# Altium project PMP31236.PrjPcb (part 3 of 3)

## Sheet PMP31236RevA_Supply_U.SchDoc: PMP30750_RevB
size 431 x 279 mm; Date: Not shown in title block; ApprovedBy: Not shown in title block; CheckedBy: Not shown in title block; Author: Not shown in title block; CompanyName: Not shown in title block; Engineer: Not shown in title block; Organization: Not shown in title block; Address1: Not shown in title block; Address2: Not shown in title block; Address3: Not shown in title block; Address4: Not shown in title block; DocumentNumber: 8; Revision: Use project parameter SCH_Rev; SheetNumber: 8; SheetTotal: 11; PageSetup: Record=PageOptions¦CenterHorizontal=True¦CenterVertical=True¦PrintScale=0.70¦XCorrection=1.00¦YCorrection=1.00¦PrintKind=0¦BorderSize=5000000¦LeftOffset=0¦BottomOffset=0¦Orientation=2¦PaperLength=1000¦PaperWidth=1000¦Scale=100¦PaperSource=15¦PrintQuality=600¦MediaType=1¦DitherType=10¦PaperKind=A4¦PrintScaleMode=1
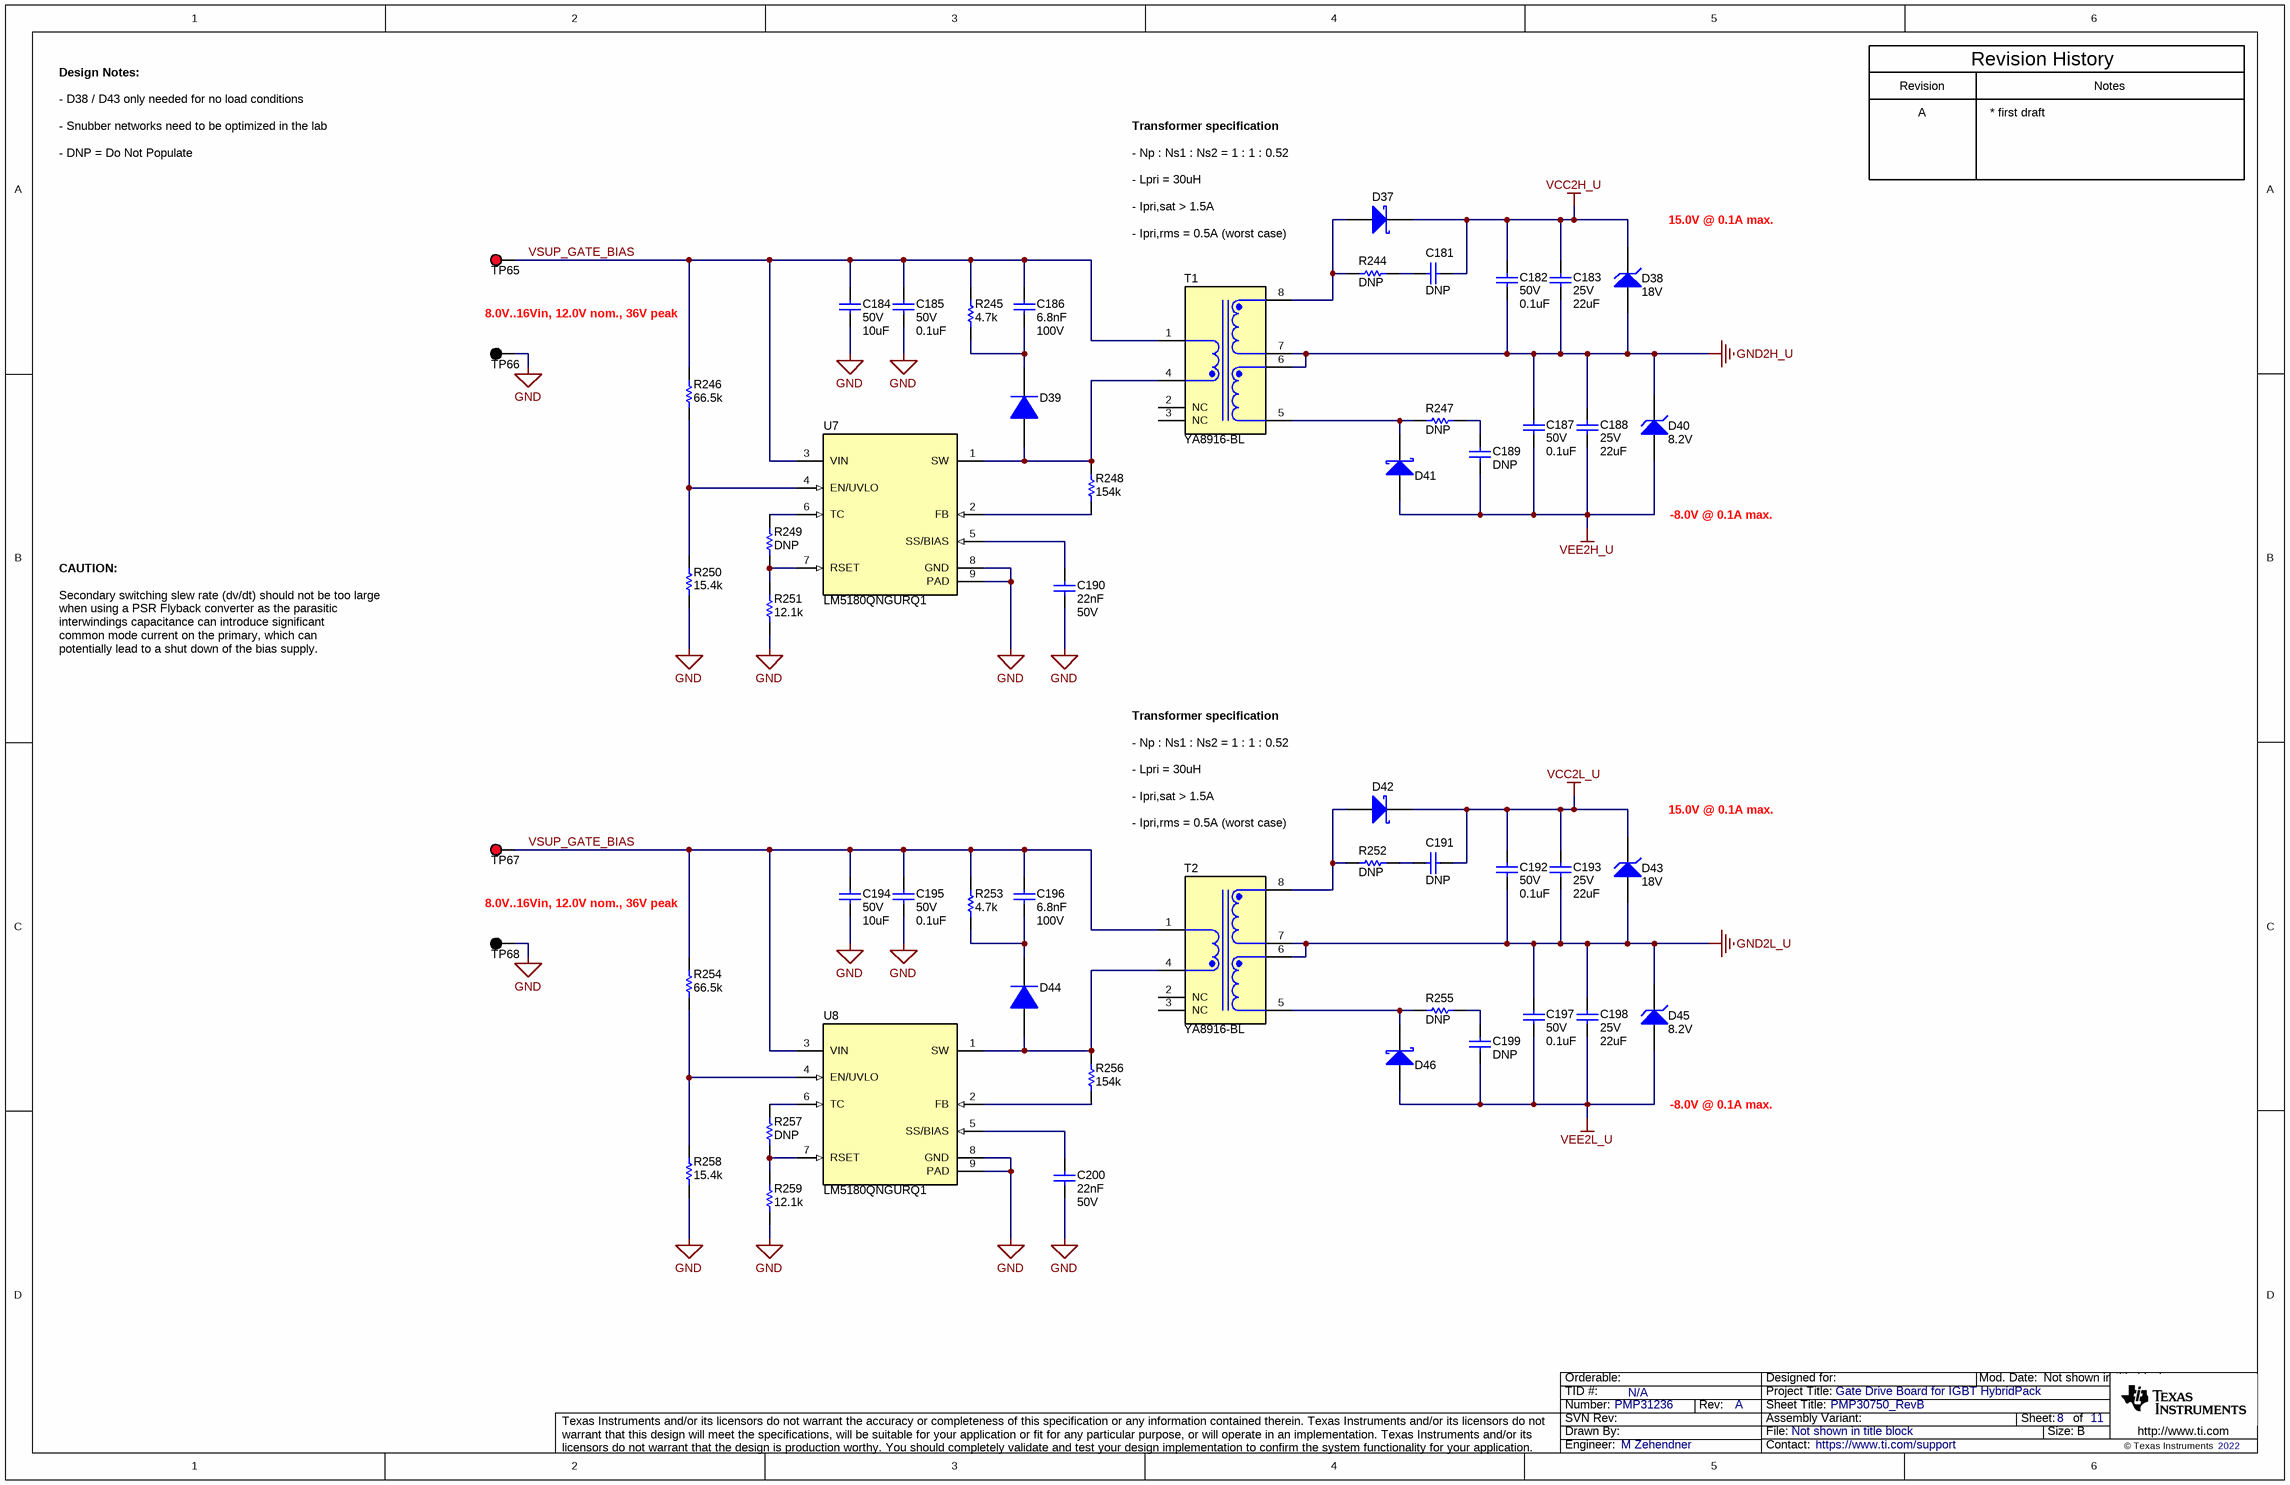
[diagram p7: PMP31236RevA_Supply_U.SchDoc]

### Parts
C181  Cap_F: DNP  [0603]  (hidden comment: GRM188R71H102KA01D)
C182  VDC_V: 50V  ValueDisplayed: 0.1uF  [0402]  (hidden comment: GRM155R71H104ME14D)
C183  VDC_V: 25V  ValueDisplayed: 22uF  [1210_270]  (hidden comment: TMK325B7226MM-PR)
C184  VDC_V: 50V  ValueDisplayed: 10uF  [1210_270]  (hidden comment: GRM32ER71H106KA12L)
C185  VDC_V: 50V  ValueDisplayed: 0.1uF  [0402]  (hidden comment: GRM155R71H104ME14D)
C186  Cap_F: 6.8nF  VDC_V: 100V  [0603]  (hidden comment: GRM188R72A682KA01D)
C187  VDC_V: 50V  ValueDisplayed: 0.1uF  [0402]  (hidden comment: GRM155R71H104ME14D)
C188  VDC_V: 25V  ValueDisplayed: 22uF  [1210_270]  (hidden comment: TMK325B7226MM-PR)
C189  Cap_F: DNP  [0603]  (hidden comment: GRM188R71H102KA01D)
C190  Cap_F: 22nF  VDC_V: 50V  [0603]  (hidden comment: GRM188R71H223KA01D)
C191  Cap_F: DNP  [0603]  (hidden comment: GRM188R71H102KA01D)
C192  VDC_V: 50V  ValueDisplayed: 0.1uF  [0402]  (hidden comment: GRM155R71H104ME14D)
C193  VDC_V: 25V  ValueDisplayed: 22uF  [1210_270]  (hidden comment: TMK325B7226MM-PR)
C194  VDC_V: 50V  ValueDisplayed: 10uF  [1210_270]  (hidden comment: GRM32ER71H106KA12L)
C195  VDC_V: 50V  ValueDisplayed: 0.1uF  [0402]  (hidden comment: GRM155R71H104ME14D)
C196  Cap_F: 6.8nF  VDC_V: 100V  [0603]  (hidden comment: GRM188R72A682KA01D)
C197  VDC_V: 50V  ValueDisplayed: 0.1uF  [0402]  (hidden comment: GRM155R71H104ME14D)
C198  VDC_V: 25V  ValueDisplayed: 22uF  [1210_270]  (hidden comment: TMK325B7226MM-PR)
C199  Cap_F: DNP  [0603]  (hidden comment: GRM188R71H102KA01D)
C200  Cap_F: 22nF  VDC_V: 50V  [0603]  (hidden comment: GRM188R71H223KA01D)
D37  PMEG6010CEH,115  [SOD-123F]  (value not drawn)
D38  value 18V  [SOD-123]  (hidden comment: MMSZ5248B-7-F)
D39  BAS16D-E3-08  [SOD-123]  (value not drawn)
D40  value 8.2V  [SOD-123]  (hidden comment: MMSZ4694-HE3-08)
D41  PMEG6010CEH,115  [SOD-123F]  (value not drawn)
D42  PMEG6010CEH,115  [SOD-123F]  (value not drawn)
D43  value 18V  [SOD-123]  (hidden comment: MMSZ5248B-7-F)
D44  BAS16D-E3-08  [SOD-123]  (value not drawn)
D45  value 8.2V  [SOD-123]  (hidden comment: MMSZ4694-HE3-08)
D46  PMEG6010CEH,115  [SOD-123F]  (value not drawn)
R244  ValueDisplayed: DNP  [0603]  (hidden comment: CRCW060310R0FKEAHP)
R245  ValueDisplayed: 4.7k  [0805_HV]  (hidden comment: CRCW08054K70JNEA)
R246  ValueDisplayed: 66.5k  [0402]  (hidden comment: CRCW040266K5FKED)
R247  ValueDisplayed: DNP  [0603]  (hidden comment: CRCW060310R0FKEAHP)
R248  ValueDisplayed: 154k  [0402]  (hidden comment: CRCW0402154KFKED)
R249  ValueDisplayed: DNP  [0402]  (hidden comment: CRCW04020000Z0ED)
R250  ValueDisplayed: 15.4k  [0402]  (hidden comment: CRCW040215K4FKED)
R251  ValueDisplayed: 12.1k  [0402]  (hidden comment: CRCW040212K1FKED)
R252  ValueDisplayed: DNP  [0603]  (hidden comment: CRCW060310R0FKEAHP)
R253  ValueDisplayed: 4.7k  [0805_HV]  (hidden comment: CRCW08054K70JNEA)
R254  ValueDisplayed: 66.5k  [0402]  (hidden comment: CRCW040266K5FKED)
R255  ValueDisplayed: DNP  [0603]  (hidden comment: CRCW060310R0FKEAHP)
R256  ValueDisplayed: 154k  [0402]  (hidden comment: CRCW0402154KFKED)
R257  ValueDisplayed: DNP  [0402]  (hidden comment: CRCW04020000Z0ED)
R258  ValueDisplayed: 15.4k  [0402]  (hidden comment: CRCW040215K4FKED)
R259  ValueDisplayed: 12.1k  [0402]  (hidden comment: CRCW040212K1FKED)
T1  YA8916-BL  [Coilcraft_YA8916-BL]
T2  YA8916-BL  [Coilcraft_YA8916-BL]
TP65  5000  [Keystone5000]  (value not drawn)
TP66  5001  [Keystone5001]  (value not drawn)
TP67  5000  [Keystone5000]  (value not drawn)
TP68  5001  [Keystone5001]  (value not drawn)
U7  LM5180QNGURQ1  [NGU0008C]
U8  LM5180QNGURQ1  [NGU0008C]

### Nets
GND: C184.2 C185.2 C190.2 C194.2 C195.2 C200.2 R250.1 R251.1 R258.1 R259.1 TP66.1 TP68.1 U7.8(GND) U7.9(PAD) U8.8(GND) U8.9(PAD)
GND2H_U: C182.2 C183.2 C187.1 C188.1 D38.2(A) D40.1(K) T1.6 T1.7
GND2L_U: C192.2 C193.2 C197.1 C198.1 D43.2(A) D45.1(K) T2.6 T2.7
VCC2H_U: C181.1 C182.1 C183.1 D37.1(K) D38.1(K)
VCC2L_U: C191.1 C192.1 C193.1 D42.1(K) D43.1(K)
VEE2H_U: C187.2 C188.2 C189.2 D40.2(A) D41.2(A)
VEE2L_U: C197.2 C198.2 C199.2 D45.2(A) D46.2(A)
VSUP_GATE_BIAS: C184.1 C185.1 C186.1 C194.1 C195.1 C196.1 R245.2 R246.2 R253.2 R254.2 T1.1 T2.1 TP65.1 TP67.1 U7.3(VIN) U8.3(VIN)
NetC181_2: C181.2 R244.2
NetC186_2: C186.2 D39.1(K) R245.1
NetC189_1: C189.1 R247.2
NetC190_1: C190.1 U7.5(SS/BIAS)
NetC191_2: C191.2 R252.2
NetC196_2: C196.2 D44.1(K) R253.1
NetC199_1: C199.1 R255.2
NetC200_1: C200.1 U8.5(SS/BIAS)
NetD37_2: D37.2(A) R244.1 T1.8
NetD39_2: D39.2(A) R248.2 T1.4 U7.1(SW)
NetD41_1: D41.1(K) R247.1 T1.5
NetD42_2: D42.2(A) R252.1 T2.8
NetD44_2: D44.2(A) R256.2 T2.4 U8.1(SW)
NetD46_1: D46.1(K) R255.1 T2.5
NetR246_1: R246.1 R250.2 U7.4(EN/UVLO)
NetR248_1: R248.1 U7.2(FB)
NetR249_1: R249.1 R251.2 U7.7(RSET)
NetR249_2: R249.2 U7.6(TC)
NetR254_1: R254.1 R258.2 U8.4(EN/UVLO)
NetR256_1: R256.1 U8.2(FB)
NetR257_1: R257.1 R259.2 U8.7(RSET)
NetR257_2: R257.2 U8.6(TC)

Not connected (* = marked no-connect by the designer): T1 2(NC) 3(NC); T2 2(NC) 3(NC)

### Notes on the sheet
- Design Notes:
- - D38 / D43 only needed for no load conditions
- Revision
- Revision History
- Notes
- - Snubber networks need to be optimized in the lab
- - DNP = Do Not Populate
- - Np : Ns1 : Ns2 = 1 : 1 : 0.52
- Transformer specification
- A
- * first draft
- - Lpri = 30uH
- - Ipri,sat > 1.5A
- - Ipri,rms = 0.5A (worst case)
- 15.0V @ 0.1A max.
- 8.0V..16Vin, 12.0V nom., 36V peak
- CAUTION:
- -8.0V @ 0.1A max.
- Secondary switching slew rate (dv/dt) should not be too large
- when using a PSR Flyback converter as the parasitic
- interwindings capacitance can introduce significant
- common mode current on the primary, which can
- potentially lead to a shut down of the bias supply.

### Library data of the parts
C181 C189 C191 C199 = CMP-0007432-5: CAP, CERM, 1000 pF, 50 V, +/- 10%, X7R, 0603; Manufacturer: MuRata; TaMin_C: -55°C; Polarized: N; SizeAreaWB_mm2: 4.68; Value1: Unknown; U/M: EA; Value: 1000pF; TaMax_C: 125°C; SizeZ_mm: 1; SizeX_mm: 1.6; SizeY_mm: 0.8; Value2: 50V; SizeArea_mm2: 1.28; AEC Category: Q200
C182 C185 C187 C192 C195 C197 = CMP-0006675-2: CAP, CERM, 0.1 uF, 50 V, +/- 20%, X7R, 0402; Manufacturer: MuRata; TaMin_C: -55°C; Polarized: N; SizeAreaWB_mm2: 3; Value1: Unknown; U/M: EA; Value: 0.1uF; TaMax_C: 125°C; SizeZ_mm: 0.6; SizeX_mm: 1; SizeY_mm: 0.5; Cap_F: 100nF; AEC Category: Q200
C183 C188 C193 C198 = CMP-0009255-2: CAP, CERM, 22 uF, 25 V, +/- 10%, X7R, AEC-Q200 Grade 1, 1210; Manufacturer: Taiyo Yuden; TaMin_C: -55°C; Polarized: N; SizeAreaWB_mm2: 14.7; Value1: Unknown; U/M: EA; Value: 22uF; TaMax_C: 125°C; SizeZ_mm: 2.7; SizeX_mm: 3.2; SizeY_mm: 2.5; Cap_Case: 1210; SizeArea_mm2: 8; AEC Qualified: Y; Cap_F: 22µF; AEC Grade: 1; AEC Category: Q200
C184 C194 = CMP-0009226-3: CAP, CERM, 10 uF, 50 V, +/- 10%, X7R, 1210; Manufacturer: MuRata; TaMin_C: -55°C; Polarized: N; SizeAreaWB_mm2: 14.7; Value1: Unknown; U/M: EA; Value: 10uF; TaMax_C: 125°C; SizeZ_mm: 2.7; SizeX_mm: 3.2; SizeY_mm: 2.5; Cap_Case: 1210; SizeArea_mm2: 8; Cap_F: 10µF; AEC Category: Q200
C186 C196 = CMP-0007487-4: CAP, CERM, 6800 pF, 100 V, +/- 10%, X7R, 0603; Manufacturer: MuRata; TaMin_C: -55°C; Polarized: N; SizeAreaWB_mm2: 4.68; Value1: Unknown; U/M: EA; Value: 6800pF; TaMax_C: 125°C; SizeZ_mm: 1; SizeX_mm: 1.6; SizeY_mm: 0.8; SizeArea_mm2: 1.28; AEC Category: Q200
C190 C200 = CMP-0007444-4: CAP, CERM, 0.022 uF, 50 V, +/- 10%, X7R, 0603; Manufacturer: MuRata; TaMin_C: -55°C; Polarized: N; SizeAreaWB_mm2: 4.68; Value1: Unknown; U/M: EA; TaMax_C: 125°C; SizeZ_mm: 1; SizeX_mm: 1.6; SizeY_mm: 0.8; SizeArea_mm2: 1.28; AEC Category: Q200
D37 D41 D42 D46 = CMP-0028377-2: Diode, Schottky, 60 V, 1 A, SOD-123F; Manufacturer: Nexperia; Value1: 1A; Value2: 0.57V; TJmax_C: 150°C; Green_REACh: Incomplete; Vr_V: 60V; SizeY_mm: 1.6; Vf_V: 570mV; SizeArea_mm2: 5.6; AEC Category: Q101; SizeZ_mm: 1.1; SizeX_mm: 3.5; Value: 60V; Green_Lifecycle: Not Set; SizeAreaWB_mm2: 11.7
D38 D43 = CMP-0005755-1: Diode, Zener, 18 V, 500 mW, SOD-123; Manufacturer: Diodes Inc.; Power_W: 500mW; SizeAreaWB_mm2: 13.095; Value1: 0.5W; RJA_CperW: 350; U/M: EA; SizeZ_mm: 1.35; SizeX_mm: 3.85; SizeY_mm: 1.7; SizeArea_mm2: 6.545; AEC Category: Q101
D39 D44 = CMP-0080761-1: Diode, Switching, 100 V, 0.25 A, AEC-Q101, SOD-123; Manufacturer: Vishay-Semiconductor; Io_A: 250mA; SizeAreaWB_mm2: 13.095; Vr_V: 100V; Value1: 0.25A; TJmax_C: 150°C; Value: 100V; SizeZ_mm: 1.35; SizeX_mm: 3.85; SizeY_mm: 1.7; Vf_V: 1.25V; SizeArea_mm2: 6.545; AEC Qualified: Y; AEC Category: Q101
D40 D45 = CMP-0077567-2: Diode, Zener, 8.2 V, 500 mW, AEC-Q101, SOD-123; Manufacturer: Vishay-Semiconductor; SizeAreaWB_mm2: 13.095; SizeX_mm: 3.85; RJA_CperW: 340; AEC Category: Q101; SizeArea_mm2: 6.545; Value1: 0.5W; SizeY_mm: 1.7; Power_W: 500mW; SizeZ_mm: 1.35; AEC Qualified: Y
R244 R247 R252 R255 = CMP-0022004-4: RES, 10.0, 1%, 0.25 W, AEC-Q200 Grade 0, 0603; Manufacturer: Vishay-Dale; Power_W: 250mW; TempCo: 100 ppm/C; Value_Code: 10R0; Value: 10.0; EIA_Code: E96; Res_ohm: 10; SizeX_mm: 1.6; SizeY_mm: 0.8; SizeZ_mm: 1; Value2: 0.25W; SizeArea_mm2: 1.28; AEC Qualified: Y; VDC_V: 75V; AEC Category: Q200; AEC Grade: 0
R245 R253 = CMP-0020559-3: RES, 4.7 k, 5%, 0.125 W, AEC-Q200 Grade 0, 0805; Manufacturer: Vishay-Dale; Power_W: 125mW; TempCo: 200 ppm/C; Value_Code: 4k70; Value: 4.7k; EIA_Code: E24; SizeX_mm: 2; SizeY_mm: 1.25; SizeZ_mm: 1.45; Value2: 0.125W; SizeArea_mm2: 2.5; AEC Qualified: Y; VDC_V: 150V; AEC Category: Q200; AEC Grade: 0
R246 R254 = CMP-0026502-2: RES, 66.5 k, 1%, 0.063 W, AEC-Q200 Grade 0, 0402; Manufacturer: Vishay-Dale; Power_W: 63mW; TempCo: 100 ppm/C; Value_Code: 66k5; Value: 66.5k; EIA_Code: E96; SizeX_mm: 1; SizeY_mm: 0.5; SizeZ_mm: 0.6; Value2: 0.063W; AEC Qualified: Y; VDC_V: 50V; AEC Category: Q200; AEC Grade: 0
R248 R256 = CMP-0026023-3: RES, 154 k, 1%, 0.063 W, AEC-Q200 Grade 0, 0402; Manufacturer: Vishay-Dale; Power_W: 63mW; TempCo: 100 ppm/C; Value: 154k; EIA_Code: E96; SizeX_mm: 1; SizeY_mm: 0.5; SizeZ_mm: 0.6; Value2: 0.063W; AEC Qualified: Y; VDC_V: 50V; AEC Category: Q200; AEC Grade: 0
R249 R257 = CMP-0026822-3: RES, 0, 5%, 0.063 W, AEC-Q200 Grade 0, 0402; Manufacturer: Vishay-Dale; Power_W: 63mW; TempCo: 200 ppm/C; Value_Code: 0000; Value: 0; EIA_Code: E24; SizeX_mm: 1; SizeY_mm: 0.5; SizeZ_mm: 0.6; Value2: 0.063W; AEC Qualified: Y; VDC_V: 50V; AEC Category: Q200
R250 R258 = CMP-0026028-3: RES, 15.4 k, 1%, 0.063 W, AEC-Q200 Grade 0, 0402; Manufacturer: Vishay-Dale; Power_W: 63mW; TempCo: 100 ppm/C; Value_Code: 15k4; Value: 15.4k; EIA_Code: E96; SizeX_mm: 1; SizeY_mm: 0.5; SizeZ_mm: 0.6; Value2: 0.063W; AEC Qualified: Y; VDC_V: 50V; AEC Category: Q200; AEC Grade: 0
R251 R259 = CMP-0025991-3: RES, 12.1 k, 1%, 0.063 W, AEC-Q200 Grade 0, 0402; Manufacturer: Vishay-Dale; Power_W: 63mW; TempCo: 100 ppm/C; Value_Code: 12k1; Value: 12.1k; EIA_Code: E96; SizeX_mm: 1; SizeY_mm: 0.5; SizeZ_mm: 0.6; Value2: 0.063W; AEC Qualified: Y; VDC_V: 50V; AEC Category: Q200; AEC Grade: 0
T1 T2 = CMP-0083973-1: Transformer, 30 uH, SMT; Manufacturer: Coilcraft; SizeAreaWB_mm2: 137.86; SizeArea_mm2: 94.86; AEC Qualified: N; Ns2toNp: 0.52; Lp: 30; AEC Category: Q200; Value: 30uH; SizeZ_mm: 10.6; Ind_H: 30µH; SizeY_mm: 10.2; Ns1toNp: 1; Rsec2_ohm: 0.392; Rsec1_ohm: 0.695; DCR_ohm: 0.36; SizeX_mm: 9.3
TP65 TP67 = CMP-0055137-1: Test Point, Miniature, Red, TH; Manufacturer: Keystone; CNHeader: FALSE; Green_Lifecycle: Active; Green_REACh: Passed; ContactFinish: Silver; CT: TRUE
TP66 TP68 = CMP-0055138-1: Test Point, Miniature, Black, TH; Manufacturer: Keystone; CNHeader: FALSE; Green_Lifecycle: Active; Green_REACh: Passed; ContactFinish: Silver; CT: TRUE
U7 U8 = CMP-0078633-2: 70-V PSR Flyback Converter With 100-V, 1.2-A Power Switch and Ultra-Low IQ, NGU0008C (WSON-8); Alternate PartNumber: LM5180QNGUTQ1; Alternate Manufacturer: Texas Instruments; SizeAreaWB_mm2: 25; SizeZ_mm: 0.8; SizeX_mm: 4; SizeArea_mm2: 16; CompType: IC; AEC Qualified: Y; AEC Category: Q200

## Sheet PMP31236RevA_Supply_V.SchDoc: PMP30750_RevB
size 431 x 279 mm; Date: Not shown in title block; ApprovedBy: Not shown in title block; CheckedBy: Not shown in title block; Author: Not shown in title block; CompanyName: Not shown in title block; Engineer: Not shown in title block; Organization: Not shown in title block; Address1: Not shown in title block; Address2: Not shown in title block; Address3: Not shown in title block; Address4: Not shown in title block; DocumentNumber: 9; Revision: Use project parameter SCH_Rev; SheetNumber: 9; SheetTotal: 11; PageSetup: Record=PageOptions¦CenterHorizontal=True¦CenterVertical=True¦PrintScale=0.70¦XCorrection=1.00¦YCorrection=1.00¦PrintKind=0¦BorderSize=5000000¦LeftOffset=0¦BottomOffset=0¦Orientation=2¦PaperLength=1000¦PaperWidth=1000¦Scale=100¦PaperSource=15¦PrintQuality=600¦MediaType=1¦DitherType=10¦PaperKind=A4¦PrintScaleMode=1
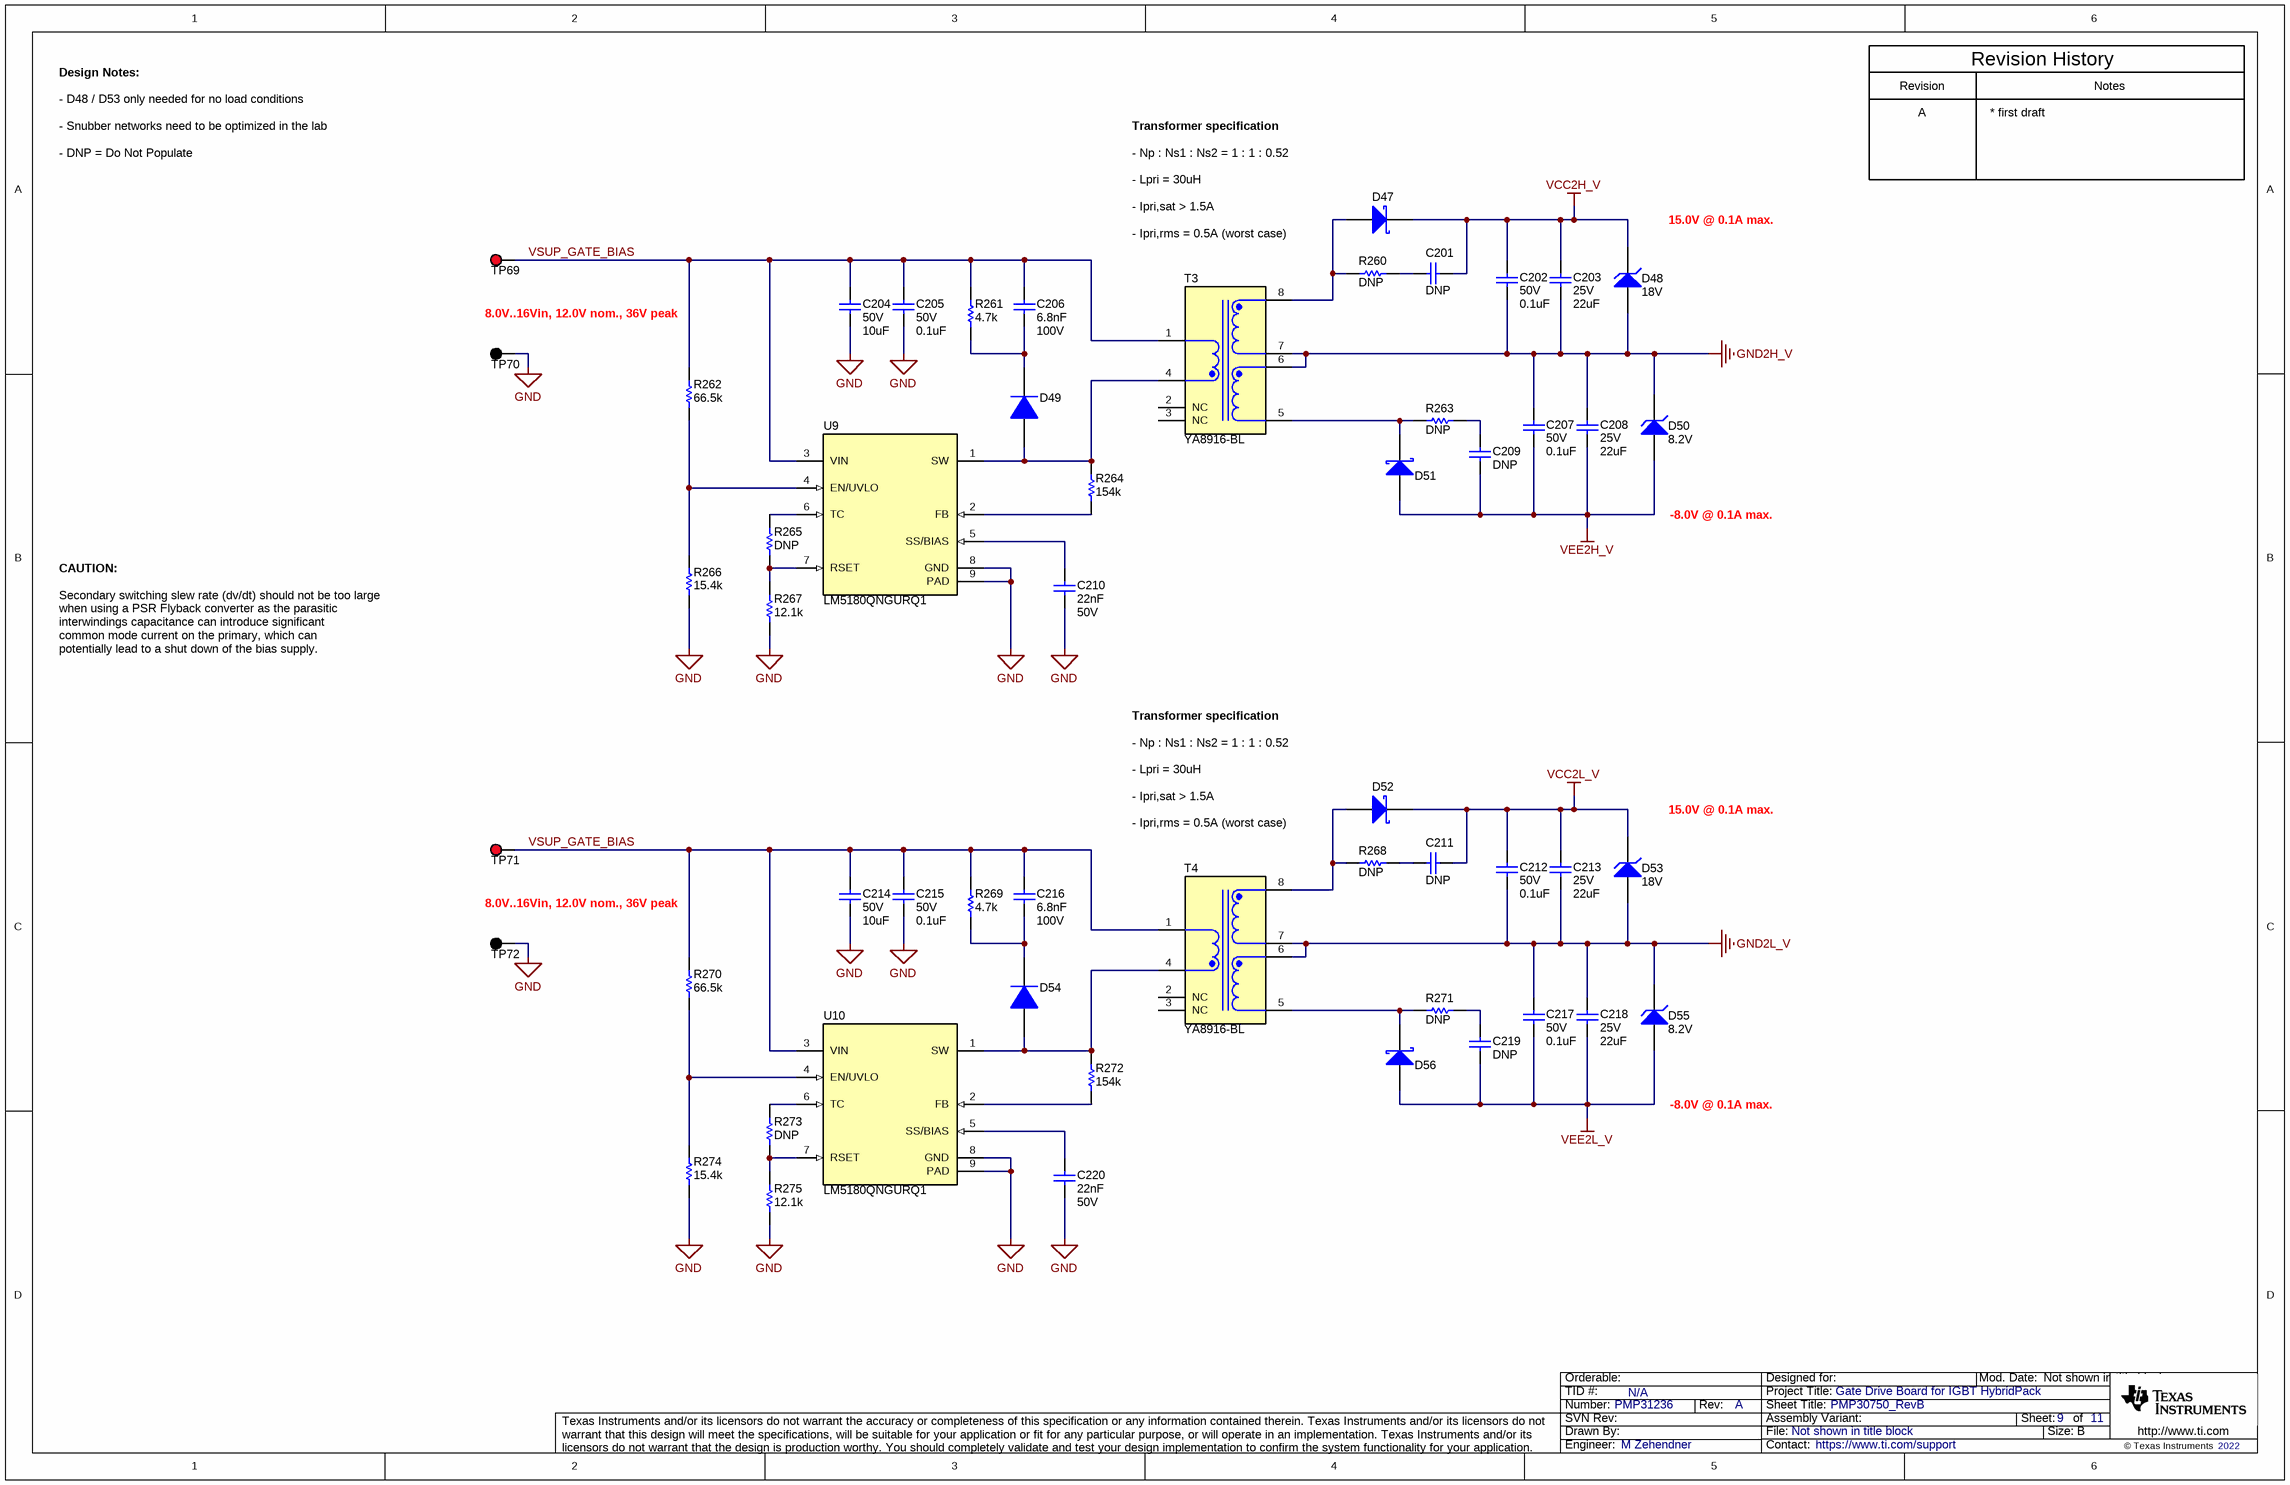
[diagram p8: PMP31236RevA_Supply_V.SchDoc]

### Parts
C201  Cap_F: DNP  [0603]  (hidden comment: GRM188R71H102KA01D)
C202  VDC_V: 50V  ValueDisplayed: 0.1uF  [0402]  (hidden comment: GRM155R71H104ME14D)
C203  VDC_V: 25V  ValueDisplayed: 22uF  [1210_270]  (hidden comment: TMK325B7226MM-PR)
C204  VDC_V: 50V  ValueDisplayed: 10uF  [1210_270]  (hidden comment: GRM32ER71H106KA12L)
C205  VDC_V: 50V  ValueDisplayed: 0.1uF  [0402]  (hidden comment: GRM155R71H104ME14D)
C206  Cap_F: 6.8nF  VDC_V: 100V  [0603]  (hidden comment: GRM188R72A682KA01D)
C207  VDC_V: 50V  ValueDisplayed: 0.1uF  [0402]  (hidden comment: GRM155R71H104ME14D)
C208  VDC_V: 25V  ValueDisplayed: 22uF  [1210_270]  (hidden comment: TMK325B7226MM-PR)
C209  Cap_F: DNP  [0603]  (hidden comment: GRM188R71H102KA01D)
C210  Cap_F: 22nF  VDC_V: 50V  [0603]  (hidden comment: GRM188R71H223KA01D)
C211  Cap_F: DNP  [0603]  (hidden comment: GRM188R71H102KA01D)
C212  VDC_V: 50V  ValueDisplayed: 0.1uF  [0402]  (hidden comment: GRM155R71H104ME14D)
C213  VDC_V: 25V  ValueDisplayed: 22uF  [1210_270]  (hidden comment: TMK325B7226MM-PR)
C214  VDC_V: 50V  ValueDisplayed: 10uF  [1210_270]  (hidden comment: GRM32ER71H106KA12L)
C215  VDC_V: 50V  ValueDisplayed: 0.1uF  [0402]  (hidden comment: GRM155R71H104ME14D)
C216  Cap_F: 6.8nF  VDC_V: 100V  [0603]  (hidden comment: GRM188R72A682KA01D)
C217  VDC_V: 50V  ValueDisplayed: 0.1uF  [0402]  (hidden comment: GRM155R71H104ME14D)
C218  VDC_V: 25V  ValueDisplayed: 22uF  [1210_270]  (hidden comment: TMK325B7226MM-PR)
C219  Cap_F: DNP  [0603]  (hidden comment: GRM188R71H102KA01D)
C220  Cap_F: 22nF  VDC_V: 50V  [0603]  (hidden comment: GRM188R71H223KA01D)
D47  PMEG6010CEH,115  [SOD-123F]  (value not drawn)
D48  value 18V  [SOD-123]  (hidden comment: MMSZ5248B-7-F)
D49  BAS16D-E3-08  [SOD-123]  (value not drawn)
D50  value 8.2V  [SOD-123]  (hidden comment: MMSZ4694-HE3-08)
D51  PMEG6010CEH,115  [SOD-123F]  (value not drawn)
D52  PMEG6010CEH,115  [SOD-123F]  (value not drawn)
D53  value 18V  [SOD-123]  (hidden comment: MMSZ5248B-7-F)
D54  BAS16D-E3-08  [SOD-123]  (value not drawn)
D55  value 8.2V  [SOD-123]  (hidden comment: MMSZ4694-HE3-08)
D56  PMEG6010CEH,115  [SOD-123F]  (value not drawn)
R260  ValueDisplayed: DNP  [0603]  (hidden comment: CRCW060310R0FKEAHP)
R261  ValueDisplayed: 4.7k  [0805_HV]  (hidden comment: CRCW08054K70JNEA)
R262  ValueDisplayed: 66.5k  [0402]  (hidden comment: CRCW040266K5FKED)
R263  ValueDisplayed: DNP  [0603]  (hidden comment: CRCW060310R0FKEAHP)
R264  ValueDisplayed: 154k  [0402]  (hidden comment: CRCW0402154KFKED)
R265  ValueDisplayed: DNP  [0402]  (hidden comment: CRCW04020000Z0ED)
R266  ValueDisplayed: 15.4k  [0402]  (hidden comment: CRCW040215K4FKED)
R267  ValueDisplayed: 12.1k  [0402]  (hidden comment: CRCW040212K1FKED)
R268  ValueDisplayed: DNP  [0603]  (hidden comment: CRCW060310R0FKEAHP)
R269  ValueDisplayed: 4.7k  [0805_HV]  (hidden comment: CRCW08054K70JNEA)
R270  ValueDisplayed: 66.5k  [0402]  (hidden comment: CRCW040266K5FKED)
R271  ValueDisplayed: DNP  [0603]  (hidden comment: CRCW060310R0FKEAHP)
R272  ValueDisplayed: 154k  [0402]  (hidden comment: CRCW0402154KFKED)
R273  ValueDisplayed: DNP  [0402]  (hidden comment: CRCW04020000Z0ED)
R274  ValueDisplayed: 15.4k  [0402]  (hidden comment: CRCW040215K4FKED)
R275  ValueDisplayed: 12.1k  [0402]  (hidden comment: CRCW040212K1FKED)
T3  YA8916-BL  [Coilcraft_YA8916-BL]
T4  YA8916-BL  [Coilcraft_YA8916-BL]
TP69  5000  [Keystone5000]  (value not drawn)
TP70  5001  [Keystone5001]  (value not drawn)
TP71  5000  [Keystone5000]  (value not drawn)
TP72  5001  [Keystone5001]  (value not drawn)
U9  LM5180QNGURQ1  [NGU0008C]
U10  LM5180QNGURQ1  [NGU0008C]

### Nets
GND: C204.2 C205.2 C210.2 C214.2 C215.2 C220.2 R266.1 R267.1 R274.1 R275.1 TP70.1 TP72.1 U9.8(GND) U9.9(PAD) U10.8(GND) U10.9(PAD)
GND2H_V: C202.2 C203.2 C207.1 C208.1 D48.2(A) D50.1(K) T3.6 T3.7
GND2L_V: C212.2 C213.2 C217.1 C218.1 D53.2(A) D55.1(K) T4.6 T4.7
VCC2H_V: C201.1 C202.1 C203.1 D47.1(K) D48.1(K)
VCC2L_V: C211.1 C212.1 C213.1 D52.1(K) D53.1(K)
VEE2H_V: C207.2 C208.2 C209.2 D50.2(A) D51.2(A)
VEE2L_V: C217.2 C218.2 C219.2 D55.2(A) D56.2(A)
VSUP_GATE_BIAS: C204.1 C205.1 C206.1 C214.1 C215.1 C216.1 R261.2 R262.2 R269.2 R270.2 T3.1 T4.1 TP69.1 TP71.1 U9.3(VIN) U10.3(VIN)
NetC201_2: C201.2 R260.2
NetC206_2: C206.2 D49.1(K) R261.1
NetC209_1: C209.1 R263.2
NetC210_1: C210.1 U9.5(SS/BIAS)
NetC211_2: C211.2 R268.2
NetC216_2: C216.2 D54.1(K) R269.1
NetC219_1: C219.1 R271.2
NetC220_1: C220.1 U10.5(SS/BIAS)
NetD47_2: D47.2(A) R260.1 T3.8
NetD49_2: D49.2(A) R264.2 T3.4 U9.1(SW)
NetD51_1: D51.1(K) R263.1 T3.5
NetD52_2: D52.2(A) R268.1 T4.8
NetD54_2: D54.2(A) R272.2 T4.4 U10.1(SW)
NetD56_1: D56.1(K) R271.1 T4.5
NetR262_1: R262.1 R266.2 U9.4(EN/UVLO)
NetR264_1: R264.1 U9.2(FB)
NetR265_1: R265.1 R267.2 U9.7(RSET)
NetR265_2: R265.2 U9.6(TC)
NetR270_1: R270.1 R274.2 U10.4(EN/UVLO)
NetR272_1: R272.1 U10.2(FB)
NetR273_1: R273.1 R275.2 U10.7(RSET)
NetR273_2: R273.2 U10.6(TC)

Not connected (* = marked no-connect by the designer): T3 2(NC) 3(NC); T4 2(NC) 3(NC)

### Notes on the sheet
- Design Notes:
- - D48 / D53 only needed for no load conditions
- Revision
- Revision History
- Notes
- - Snubber networks need to be optimized in the lab
- - DNP = Do Not Populate
- - Np : Ns1 : Ns2 = 1 : 1 : 0.52
- Transformer specification
- A
- * first draft
- - Lpri = 30uH
- - Ipri,sat > 1.5A
- - Ipri,rms = 0.5A (worst case)
- 15.0V @ 0.1A max.
- 8.0V..16Vin, 12.0V nom., 36V peak
- CAUTION:
- -8.0V @ 0.1A max.
- Secondary switching slew rate (dv/dt) should not be too large
- when using a PSR Flyback converter as the parasitic
- interwindings capacitance can introduce significant
- common mode current on the primary, which can
- potentially lead to a shut down of the bias supply.

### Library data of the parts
C201 C209 C211 C219 = CMP-0007432-5: as C181 on sheet PMP31236RevA_Supply_U
C202 C205 C207 C212 C215 C217 = CMP-0006675-2: as C182 on sheet PMP31236RevA_Supply_U
C203 C208 C213 C218 = CMP-0009255-2: as C183 on sheet PMP31236RevA_Supply_U
C204 C214 = CMP-0009226-3: as C184 on sheet PMP31236RevA_Supply_U
C206 C216 = CMP-0007487-4: as C186 on sheet PMP31236RevA_Supply_U
C210 C220 = CMP-0007444-4: as C190 on sheet PMP31236RevA_Supply_U
D47 D51 D52 D56 = CMP-0028377-2: as D37 on sheet PMP31236RevA_Supply_U
D48 D53 = CMP-0005755-1: as D38 on sheet PMP31236RevA_Supply_U
D49 D54 = CMP-0080761-1: as D39 on sheet PMP31236RevA_Supply_U
D50 D55 = CMP-0077567-2: as D40 on sheet PMP31236RevA_Supply_U
R260 R263 R268 R271 = CMP-0022004-4: as R244 on sheet PMP31236RevA_Supply_U
R261 R269 = CMP-0020559-3: as R245 on sheet PMP31236RevA_Supply_U
R262 R270 = CMP-0026502-2: as R246 on sheet PMP31236RevA_Supply_U
R264 R272 = CMP-0026023-3: as R248 on sheet PMP31236RevA_Supply_U
R265 R273 = CMP-0026822-3: as R249 on sheet PMP31236RevA_Supply_U
R266 R274 = CMP-0026028-3: as R250 on sheet PMP31236RevA_Supply_U
R267 R275 = CMP-0025991-3: as R251 on sheet PMP31236RevA_Supply_U
T3 T4 = CMP-0083973-1: as T1 on sheet PMP31236RevA_Supply_U
TP69 TP71 = CMP-0055137-1: as TP65 on sheet PMP31236RevA_Supply_U
TP70 TP72 = CMP-0055138-1: as TP66 on sheet PMP31236RevA_Supply_U
U9 U10 = CMP-0078633-2: as U7 on sheet PMP31236RevA_Supply_U

## Sheet PMP31236RevA_Supply_W.SchDoc: PMP30750_RevB
size 431 x 279 mm; Date: Not shown in title block; ApprovedBy: Not shown in title block; CheckedBy: Not shown in title block; Author: Not shown in title block; CompanyName: Not shown in title block; Engineer: Not shown in title block; Organization: Not shown in title block; Address1: Not shown in title block; Address2: Not shown in title block; Address3: Not shown in title block; Address4: Not shown in title block; DocumentNumber: 10; Revision: Use project parameter SCH_Rev; SheetNumber: 10; SheetTotal: 11; PageSetup: Record=PageOptions¦CenterHorizontal=True¦CenterVertical=True¦PrintScale=0.70¦XCorrection=1.00¦YCorrection=1.00¦PrintKind=0¦BorderSize=5000000¦LeftOffset=0¦BottomOffset=0¦Orientation=2¦PaperLength=1000¦PaperWidth=1000¦Scale=100¦PaperSource=15¦PrintQuality=600¦MediaType=1¦DitherType=10¦PaperKind=A4¦PrintScaleMode=1
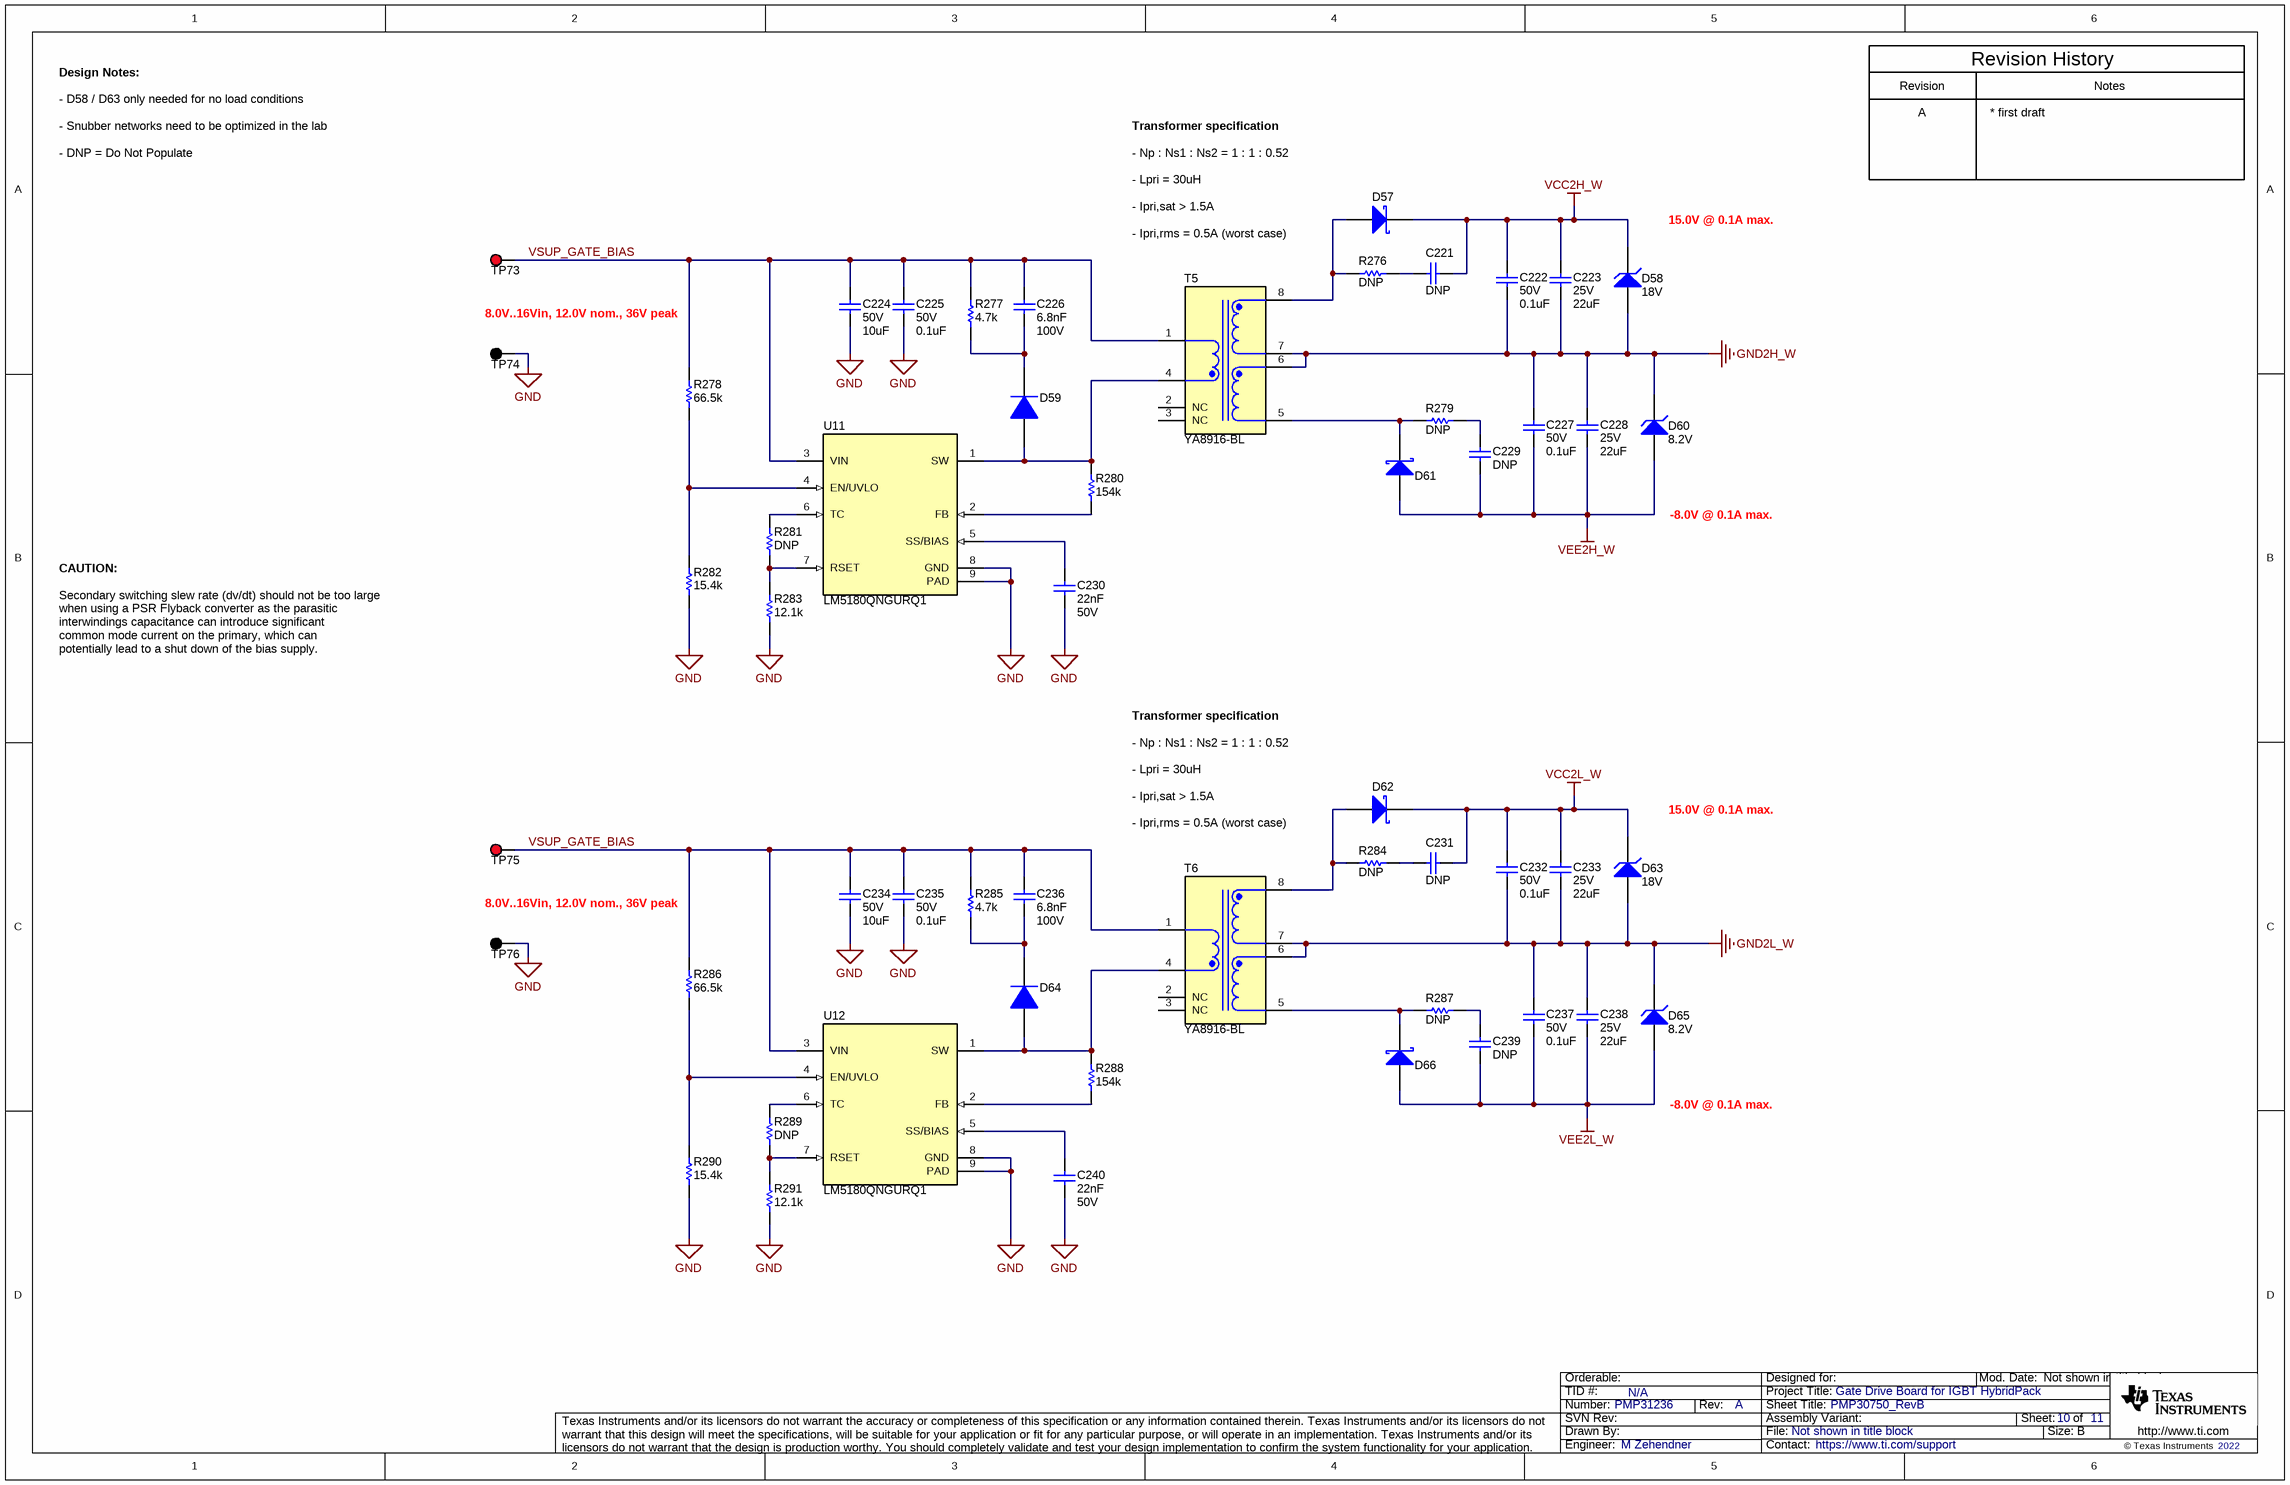
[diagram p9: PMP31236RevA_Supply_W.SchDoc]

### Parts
C221  Cap_F: DNP  [0603]  (hidden comment: GRM188R71H102KA01D)
C222  VDC_V: 50V  ValueDisplayed: 0.1uF  [0402]  (hidden comment: GRM155R71H104ME14D)
C223  VDC_V: 25V  ValueDisplayed: 22uF  [1210_270]  (hidden comment: TMK325B7226MM-PR)
C224  VDC_V: 50V  ValueDisplayed: 10uF  [1210_270]  (hidden comment: GRM32ER71H106KA12L)
C225  VDC_V: 50V  ValueDisplayed: 0.1uF  [0402]  (hidden comment: GRM155R71H104ME14D)
C226  Cap_F: 6.8nF  VDC_V: 100V  [0603]  (hidden comment: GRM188R72A682KA01D)
C227  VDC_V: 50V  ValueDisplayed: 0.1uF  [0402]  (hidden comment: GRM155R71H104ME14D)
C228  VDC_V: 25V  ValueDisplayed: 22uF  [1210_270]  (hidden comment: TMK325B7226MM-PR)
C229  Cap_F: DNP  [0603]  (hidden comment: GRM188R71H102KA01D)
C230  Cap_F: 22nF  VDC_V: 50V  [0603]  (hidden comment: GRM188R71H223KA01D)
C231  Cap_F: DNP  [0603]  (hidden comment: GRM188R71H102KA01D)
C232  VDC_V: 50V  ValueDisplayed: 0.1uF  [0402]  (hidden comment: GRM155R71H104ME14D)
C233  VDC_V: 25V  ValueDisplayed: 22uF  [1210_270]  (hidden comment: TMK325B7226MM-PR)
C234  VDC_V: 50V  ValueDisplayed: 10uF  [1210_270]  (hidden comment: GRM32ER71H106KA12L)
C235  VDC_V: 50V  ValueDisplayed: 0.1uF  [0402]  (hidden comment: GRM155R71H104ME14D)
C236  Cap_F: 6.8nF  VDC_V: 100V  [0603]  (hidden comment: GRM188R72A682KA01D)
C237  VDC_V: 50V  ValueDisplayed: 0.1uF  [0402]  (hidden comment: GRM155R71H104ME14D)
C238  VDC_V: 25V  ValueDisplayed: 22uF  [1210_270]  (hidden comment: TMK325B7226MM-PR)
C239  Cap_F: DNP  [0603]  (hidden comment: GRM188R71H102KA01D)
C240  Cap_F: 22nF  VDC_V: 50V  [0603]  (hidden comment: GRM188R71H223KA01D)
D57  PMEG6010CEH,115  [SOD-123F]  (value not drawn)
D58  value 18V  [SOD-123]  (hidden comment: MMSZ5248B-7-F)
D59  BAS16D-E3-08  [SOD-123]  (value not drawn)
D60  value 8.2V  [SOD-123]  (hidden comment: MMSZ4694-HE3-08)
D61  PMEG6010CEH,115  [SOD-123F]  (value not drawn)
D62  PMEG6010CEH,115  [SOD-123F]  (value not drawn)
D63  value 18V  [SOD-123]  (hidden comment: MMSZ5248B-7-F)
D64  BAS16D-E3-08  [SOD-123]  (value not drawn)
D65  value 8.2V  [SOD-123]  (hidden comment: MMSZ4694-HE3-08)
D66  PMEG6010CEH,115  [SOD-123F]  (value not drawn)
R276  ValueDisplayed: DNP  [0603]  (hidden comment: CRCW060310R0FKEAHP)
R277  ValueDisplayed: 4.7k  [0805_HV]  (hidden comment: CRCW08054K70JNEA)
R278  ValueDisplayed: 66.5k  [0402]  (hidden comment: CRCW040266K5FKED)
R279  ValueDisplayed: DNP  [0603]  (hidden comment: CRCW060310R0FKEAHP)
R280  ValueDisplayed: 154k  [0402]  (hidden comment: CRCW0402154KFKED)
R281  ValueDisplayed: DNP  [0402]  (hidden comment: CRCW04020000Z0ED)
R282  ValueDisplayed: 15.4k  [0402]  (hidden comment: CRCW040215K4FKED)
R283  ValueDisplayed: 12.1k  [0402]  (hidden comment: CRCW040212K1FKED)
R284  ValueDisplayed: DNP  [0603]  (hidden comment: CRCW060310R0FKEAHP)
R285  ValueDisplayed: 4.7k  [0805_HV]  (hidden comment: CRCW08054K70JNEA)
R286  ValueDisplayed: 66.5k  [0402]  (hidden comment: CRCW040266K5FKED)
R287  ValueDisplayed: DNP  [0603]  (hidden comment: CRCW060310R0FKEAHP)
R288  ValueDisplayed: 154k  [0402]  (hidden comment: CRCW0402154KFKED)
R289  ValueDisplayed: DNP  [0402]  (hidden comment: CRCW04020000Z0ED)
R290  ValueDisplayed: 15.4k  [0402]  (hidden comment: CRCW040215K4FKED)
R291  ValueDisplayed: 12.1k  [0402]  (hidden comment: CRCW040212K1FKED)
T5  YA8916-BL  [Coilcraft_YA8916-BL]
T6  YA8916-BL  [Coilcraft_YA8916-BL]
TP73  5000  [Keystone5000]  (value not drawn)
TP74  5001  [Keystone5001]  (value not drawn)
TP75  5000  [Keystone5000]  (value not drawn)
TP76  5001  [Keystone5001]  (value not drawn)
U11  LM5180QNGURQ1  [NGU0008C]
U12  LM5180QNGURQ1  [NGU0008C]

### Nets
GND: C224.2 C225.2 C230.2 C234.2 C235.2 C240.2 R282.1 R283.1 R290.1 R291.1 TP74.1 TP76.1 U11.8(GND) U11.9(PAD) U12.8(GND) U12.9(PAD)
GND2H_W: C222.2 C223.2 C227.1 C228.1 D58.2(A) D60.1(K) T5.6 T5.7
GND2L_W: C232.2 C233.2 C237.1 C238.1 D63.2(A) D65.1(K) T6.6 T6.7
VCC2H_W: C221.1 C222.1 C223.1 D57.1(K) D58.1(K)
VCC2L_W: C231.1 C232.1 C233.1 D62.1(K) D63.1(K)
VEE2H_W: C227.2 C228.2 C229.2 D60.2(A) D61.2(A)
VEE2L_W: C237.2 C238.2 C239.2 D65.2(A) D66.2(A)
VSUP_GATE_BIAS: C224.1 C225.1 C226.1 C234.1 C235.1 C236.1 R277.2 R278.2 R285.2 R286.2 T5.1 T6.1 TP73.1 TP75.1 U11.3(VIN) U12.3(VIN)
NetC221_2: C221.2 R276.2
NetC226_2: C226.2 D59.1(K) R277.1
NetC229_1: C229.1 R279.2
NetC230_1: C230.1 U11.5(SS/BIAS)
NetC231_2: C231.2 R284.2
NetC236_2: C236.2 D64.1(K) R285.1
NetC239_1: C239.1 R287.2
NetC240_1: C240.1 U12.5(SS/BIAS)
NetD57_2: D57.2(A) R276.1 T5.8
NetD59_2: D59.2(A) R280.2 T5.4 U11.1(SW)
NetD61_1: D61.1(K) R279.1 T5.5
NetD62_2: D62.2(A) R284.1 T6.8
NetD64_2: D64.2(A) R288.2 T6.4 U12.1(SW)
NetD66_1: D66.1(K) R287.1 T6.5
NetR278_1: R278.1 R282.2 U11.4(EN/UVLO)
NetR280_1: R280.1 U11.2(FB)
NetR281_1: R281.1 R283.2 U11.7(RSET)
NetR281_2: R281.2 U11.6(TC)
NetR286_1: R286.1 R290.2 U12.4(EN/UVLO)
NetR288_1: R288.1 U12.2(FB)
NetR289_1: R289.1 R291.2 U12.7(RSET)
NetR289_2: R289.2 U12.6(TC)

Not connected (* = marked no-connect by the designer): T5 2(NC) 3(NC); T6 2(NC) 3(NC)

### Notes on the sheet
- Design Notes:
- - D58 / D63 only needed for no load conditions
- Revision
- Revision History
- Notes
- - Snubber networks need to be optimized in the lab
- - DNP = Do Not Populate
- - Np : Ns1 : Ns2 = 1 : 1 : 0.52
- Transformer specification
- A
- * first draft
- - Lpri = 30uH
- - Ipri,sat > 1.5A
- - Ipri,rms = 0.5A (worst case)
- 15.0V @ 0.1A max.
- 8.0V..16Vin, 12.0V nom., 36V peak
- CAUTION:
- -8.0V @ 0.1A max.
- Secondary switching slew rate (dv/dt) should not be too large
- when using a PSR Flyback converter as the parasitic
- interwindings capacitance can introduce significant
- common mode current on the primary, which can
- potentially lead to a shut down of the bias supply.

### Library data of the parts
C221 C229 C231 C239 = CMP-0007432-5: as C181 on sheet PMP31236RevA_Supply_U
C222 C225 C227 C232 C235 C237 = CMP-0006675-2: as C182 on sheet PMP31236RevA_Supply_U
C223 C228 C233 C238 = CMP-0009255-2: as C183 on sheet PMP31236RevA_Supply_U
C224 C234 = CMP-0009226-3: as C184 on sheet PMP31236RevA_Supply_U
C226 C236 = CMP-0007487-4: as C186 on sheet PMP31236RevA_Supply_U
C230 C240 = CMP-0007444-4: as C190 on sheet PMP31236RevA_Supply_U
D57 D61 D62 D66 = CMP-0028377-2: as D37 on sheet PMP31236RevA_Supply_U
D58 D63 = CMP-0005755-1: as D38 on sheet PMP31236RevA_Supply_U
D59 D64 = CMP-0080761-1: as D39 on sheet PMP31236RevA_Supply_U
D60 D65 = CMP-0077567-2: as D40 on sheet PMP31236RevA_Supply_U
R276 R279 R284 R287 = CMP-0022004-4: as R244 on sheet PMP31236RevA_Supply_U
R277 R285 = CMP-0020559-3: as R245 on sheet PMP31236RevA_Supply_U
R278 R286 = CMP-0026502-2: as R246 on sheet PMP31236RevA_Supply_U
R280 R288 = CMP-0026023-3: as R248 on sheet PMP31236RevA_Supply_U
R281 R289 = CMP-0026822-3: as R249 on sheet PMP31236RevA_Supply_U
R282 R290 = CMP-0026028-3: as R250 on sheet PMP31236RevA_Supply_U
R283 R291 = CMP-0025991-3: as R251 on sheet PMP31236RevA_Supply_U
T5 T6 = CMP-0083973-1: as T1 on sheet PMP31236RevA_Supply_U
TP73 TP75 = CMP-0055137-1: as TP65 on sheet PMP31236RevA_Supply_U
TP74 TP76 = CMP-0055138-1: as TP66 on sheet PMP31236RevA_Supply_U
U11 U12 = CMP-0078633-2: as U7 on sheet PMP31236RevA_Supply_U

## Sheet PMP31236RevA_IGBT_Module.SchDoc
size A4; Date: Not shown in title block; ApprovedBy: Not shown in title block; CheckedBy: Not shown in title block; Author: Not shown in title block; CompanyName: Not shown in title block; Engineer: Not shown in title block; Organization: Not shown in title block; Address1: Not shown in title block; Address2: Not shown in title block; Address3: Not shown in title block; Address4: Not shown in title block; DocumentNumber: 6; Revision: Use project parameter SCH_Rev; SheetNumber: 11; SheetTotal: 11; PageSetup: Record=PageOptions¦CenterHorizontal=True¦CenterVertical=True¦PrintScale=0.93¦XCorrection=1.00¦YCorrection=1.00¦PrintKind=0¦BorderSize=5000000¦LeftOffset=0¦BottomOffset=0¦Orientation=2¦PaperLength=1000¦PaperWidth=1000¦Scale=100¦PaperSource=15¦PrintQuality=600¦MediaType=1¦DitherType=10¦PaperKind=Letter¦PrintScaleMode=1
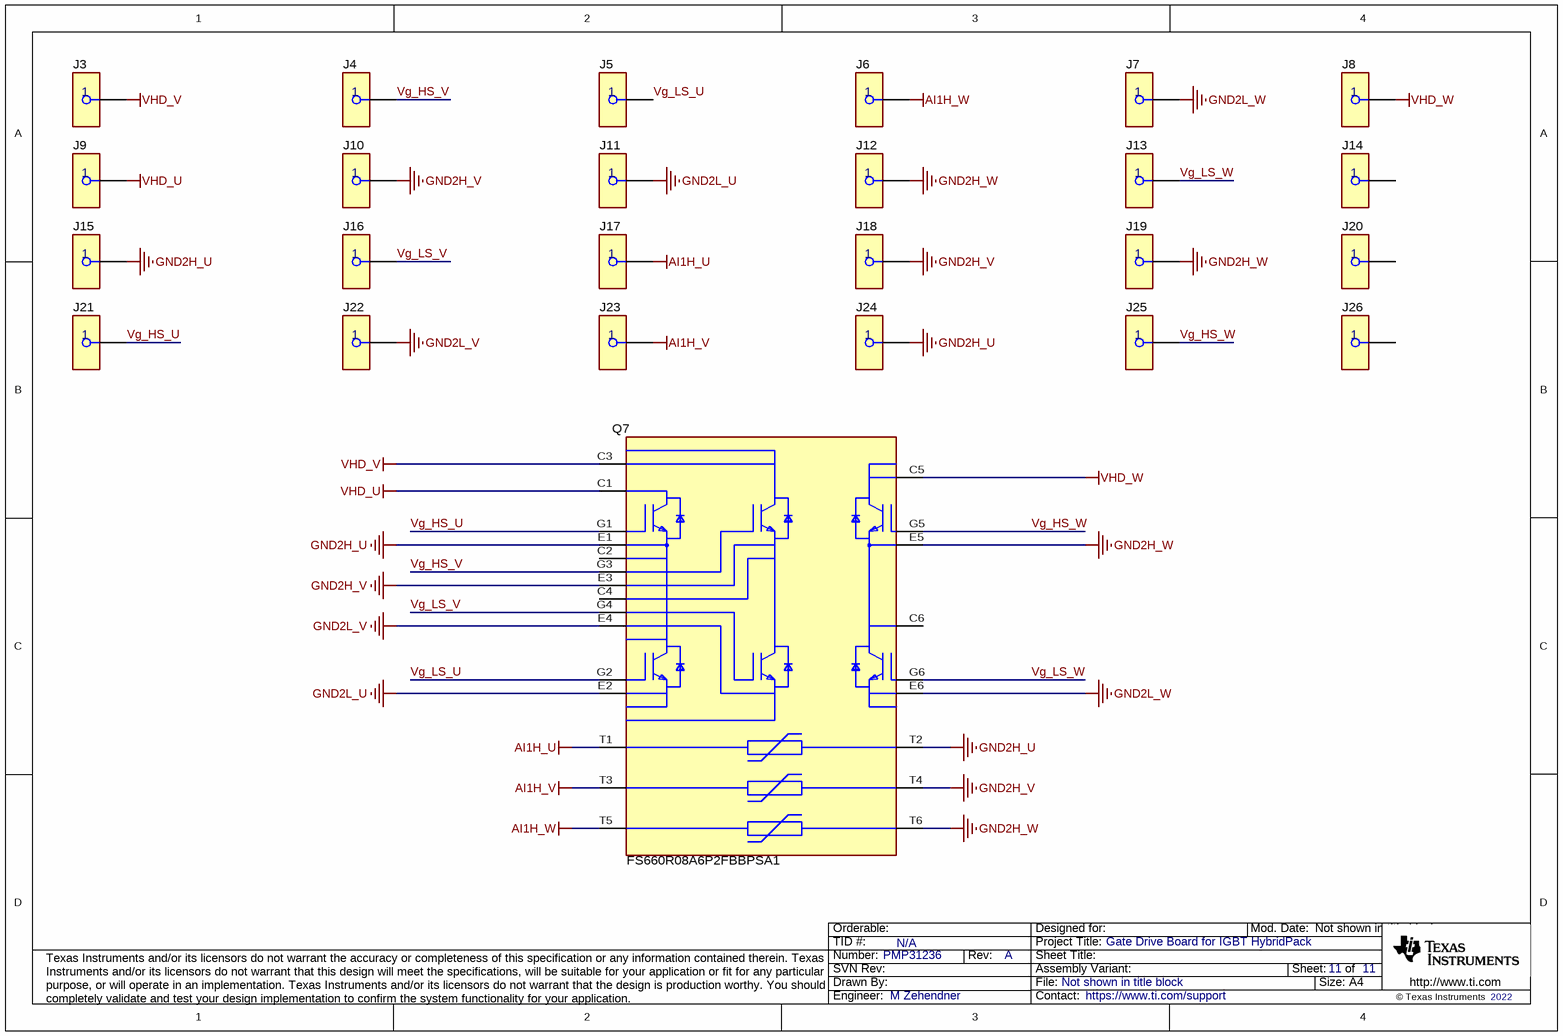
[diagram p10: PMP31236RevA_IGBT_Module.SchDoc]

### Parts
J3  0405-0-15-15-34-27-04-0  [FP-0405-0-15-15-34-27-04-0_HDR1-MFG]  (value not drawn)
J4  0405-0-15-15-34-27-04-0  [FP-0405-0-15-15-34-27-04-0_HDR1-MFG]  (value not drawn)
J5  0405-0-15-15-34-27-04-0  [FP-0405-0-15-15-34-27-04-0_HDR1-MFG]  (value not drawn)
J6  0405-0-15-15-34-27-04-0  [FP-0405-0-15-15-34-27-04-0_HDR1-MFG]  (value not drawn)
J7  0405-0-15-15-34-27-04-0  [FP-0405-0-15-15-34-27-04-0_HDR1-MFG]  (value not drawn)
J8  0405-0-15-15-34-27-04-0  [FP-0405-0-15-15-34-27-04-0_HDR1-MFG]  (value not drawn)
J9  0405-0-15-15-34-27-04-0  [FP-0405-0-15-15-34-27-04-0_HDR1-MFG]  (value not drawn)
J10  0405-0-15-15-34-27-04-0  [FP-0405-0-15-15-34-27-04-0_HDR1-MFG]  (value not drawn)
J11  0405-0-15-15-34-27-04-0  [FP-0405-0-15-15-34-27-04-0_HDR1-MFG]  (value not drawn)
J12  0405-0-15-15-34-27-04-0  [FP-0405-0-15-15-34-27-04-0_HDR1-MFG]  (value not drawn)
J13  0405-0-15-15-34-27-04-0  [FP-0405-0-15-15-34-27-04-0_HDR1-MFG]  (value not drawn)
J14  0405-0-15-15-34-27-04-0  [FP-0405-0-15-15-34-27-04-0_HDR1-MFG]  (value not drawn)
J15  0405-0-15-15-34-27-04-0  [FP-0405-0-15-15-34-27-04-0_HDR1-MFG]  (value not drawn)
J16  0405-0-15-15-34-27-04-0  [FP-0405-0-15-15-34-27-04-0_HDR1-MFG]  (value not drawn)
J17  0405-0-15-15-34-27-04-0  [FP-0405-0-15-15-34-27-04-0_HDR1-MFG]  (value not drawn)
J18  0405-0-15-15-34-27-04-0  [FP-0405-0-15-15-34-27-04-0_HDR1-MFG]  (value not drawn)
J19  0405-0-15-15-34-27-04-0  [FP-0405-0-15-15-34-27-04-0_HDR1-MFG]  (value not drawn)
J20  0405-0-15-15-34-27-04-0  [FP-0405-0-15-15-34-27-04-0_HDR1-MFG]  (value not drawn)
J21  0405-0-15-15-34-27-04-0  [FP-0405-0-15-15-34-27-04-0_HDR1-MFG]  (value not drawn)
J22  0405-0-15-15-34-27-04-0  [FP-0405-0-15-15-34-27-04-0_HDR1-MFG]  (value not drawn)
J23  0405-0-15-15-34-27-04-0  [FP-0405-0-15-15-34-27-04-0_HDR1-MFG]  (value not drawn)
J24  0405-0-15-15-34-27-04-0  [FP-0405-0-15-15-34-27-04-0_HDR1-MFG]  (value not drawn)
J25  0405-0-15-15-34-27-04-0  [FP-0405-0-15-15-34-27-04-0_HDR1-MFG]  (value not drawn)
J26  0405-0-15-15-34-27-04-0  [FP-0405-0-15-15-34-27-04-0_HDR1-MFG]  (value not drawn)
Q7  FS660R08A6P2FBBPSA1  [FP-FS660R08A6P2FBBPSA1_PTH_MD_1554MM5_100MM5-MFG]

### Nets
AI1H_U: J17.1 Q7.T1
AI1H_V: J23.1 Q7.T3
AI1H_W: J6.1 Q7.T5
GND2H_U: J15.1 J24.1 Q7.E1 Q7.T2
GND2H_V: J10.1 J18.1 Q7.E3 Q7.T4
GND2H_W: J12.1 J19.1 Q7.E5 Q7.T6
GND2L_U: J11.1 Q7.E2
GND2L_V: J22.1 Q7.E4
GND2L_W: J7.1 Q7.E6
Vg_HS_U: J21.1 Q7.G1
Vg_HS_V: J4.1 Q7.G3
Vg_HS_W: J25.1 Q7.G5
Vg_LS_U: J5.1 Q7.G2
Vg_LS_V: J16.1 Q7.G4
Vg_LS_W: J13.1 Q7.G6
VHD_U: J9.1 Q7.C1
VHD_V: J3.1 Q7.C3
VHD_W: J8.1 Q7.C5

Not connected (* = marked no-connect by the designer): J14 1; J20 1; J26 1; Q7 C2 C4 C6

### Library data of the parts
J3-J26 = CMP-0087418-2: CONN PIN RCPT .032-.046 PRESSFIT; Manufacturer: Mill-Max; ContactFinish: Gold,Nickel; Current_A: 8A; Symbol Name: SYM-0405-0-15-15-34-27-04-0
Q7 = CMP-0098118-1: IGBT Module Trench Field Stop Three Phase Inverter 750 V 450 A 1053 W Chassis Mount AG-HYBRIDD-1; Manufacturer: Infineon; Value: 750V; Vcesat1_V: 1.1V; Power_W: 1053W; Turn On Delay Time: 0.28us; Turn Off Delay Time: 0.94us; TJmax_C: +150°C; Collector Current: 450A; AEC Qualified: No

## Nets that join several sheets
AI1H_U: PMP31236RevA_HS_U (R33.2 R36.2 TP7.1), PMP31236RevA_IGBT_Module (J17.1 Q7.T1)
AI1H_V: PMP31236RevA_HS_V (R71.2 R74.2 TP18.1), PMP31236RevA_IGBT_Module (J23.1 Q7.T3)
AI1H_W: PMP31236RevA_HS_W (R109.2 R112.2 TP28.1), PMP31236RevA_IGBT_Module (J6.1 Q7.T5)
GND: PMP31236RevA_HS_U (20 pins), PMP31236RevA_HS_V (19 pins), PMP31236RevA_HS_W (19 pins), PMP31236RevA_LS_U (19 pins), PMP31236RevA_LS_V (19 pins), PMP31236RevA_LS_W (19 pins), PMP31236RevA_Interface (18 pins), PMP31236RevA_Supply_U (16 pins), PMP31236RevA_Supply_V (16 pins), PMP31236RevA_Supply_W (16 pins)
GND2H_U: PMP31236RevA_HS_U (18 pins), PMP31236RevA_LS_U (D19.1 D22.1), PMP31236RevA_Supply_U (8 pins), PMP31236RevA_IGBT_Module (J15.1 J24.1 Q7.E1 Q7.T2)
GND2H_V: PMP31236RevA_HS_V (18 pins), PMP31236RevA_LS_V (D25.1 D28.1), PMP31236RevA_Supply_V (8 pins), PMP31236RevA_IGBT_Module (J10.1 J18.1 Q7.E3 Q7.T4)
GND2H_W: PMP31236RevA_HS_W (18 pins), PMP31236RevA_LS_W (D31.1 D34.1), PMP31236RevA_Supply_W (8 pins), PMP31236RevA_IGBT_Module (J12.1 J19.1 Q7.E5 Q7.T6)
GND2L_U: PMP31236RevA_LS_U (18 pins), PMP31236RevA_Supply_U (8 pins), PMP31236RevA_IGBT_Module (J11.1 Q7.E2)
GND2L_V: PMP31236RevA_LS_V (18 pins), PMP31236RevA_Supply_V (8 pins), PMP31236RevA_IGBT_Module (J22.1 Q7.E4)
GND2L_W: PMP31236RevA_LS_W (18 pins), PMP31236RevA_Supply_W (8 pins), PMP31236RevA_IGBT_Module (J7.1 Q7.E6)
VCC2H_U: PMP31236RevA_HS_U (7 pins), PMP31236RevA_Supply_U (5 pins)
VCC2H_V: PMP31236RevA_HS_V (7 pins), PMP31236RevA_Supply_V (5 pins)
VCC2H_W: PMP31236RevA_HS_W (7 pins), PMP31236RevA_Supply_W (5 pins)
VCC2L_U: PMP31236RevA_LS_U (7 pins), PMP31236RevA_Supply_U (5 pins)
VCC2L_V: PMP31236RevA_LS_V (7 pins), PMP31236RevA_Supply_V (5 pins)
VCC2L_W: PMP31236RevA_LS_W (7 pins), PMP31236RevA_Supply_W (5 pins)
VEE2H_U: PMP31236RevA_HS_U (11 pins), PMP31236RevA_Supply_U (5 pins)
VEE2H_V: PMP31236RevA_HS_V (11 pins), PMP31236RevA_Supply_V (5 pins)
VEE2H_W: PMP31236RevA_HS_W (11 pins), PMP31236RevA_Supply_W (5 pins)
VEE2L_U: PMP31236RevA_LS_U (9 pins), PMP31236RevA_Supply_U (5 pins)
VEE2L_V: PMP31236RevA_LS_V (11 pins), PMP31236RevA_Supply_V (5 pins)
VEE2L_W: PMP31236RevA_LS_W (11 pins), PMP31236RevA_Supply_W (5 pins)
Vg_HS_U: PMP31236RevA_HS_U (15 pins), PMP31236RevA_IGBT_Module (J21.1 Q7.G1)
Vg_HS_V: PMP31236RevA_HS_V (15 pins), PMP31236RevA_IGBT_Module (J4.1 Q7.G3)
Vg_HS_W: PMP31236RevA_HS_W (15 pins), PMP31236RevA_IGBT_Module (J25.1 Q7.G5)
Vg_LS_U: PMP31236RevA_LS_U (15 pins), PMP31236RevA_IGBT_Module (J5.1 Q7.G2)
Vg_LS_V: PMP31236RevA_LS_V (15 pins), PMP31236RevA_IGBT_Module (J16.1 Q7.G4)
Vg_LS_W: PMP31236RevA_LS_W (15 pins), PMP31236RevA_IGBT_Module (J13.1 Q7.G6)
VHD_U: PMP31236RevA_HS_U (D1.1 D4.1), PMP31236RevA_LS_U (R151.2 TP39.1), PMP31236RevA_IGBT_Module (J9.1 Q7.C1)
VHD_V: PMP31236RevA_HS_V (D7.1 D10.1), PMP31236RevA_LS_V (R194.2 TP50.1), PMP31236RevA_IGBT_Module (J3.1 Q7.C3)
VHD_W: PMP31236RevA_HS_W (D13.1 D16.1), PMP31236RevA_LS_W (R237.2 TP61.1), PMP31236RevA_IGBT_Module (J8.1 Q7.C5)
ASC_EN_PRI: PMP31236RevA_HS_U (R22.1), PMP31236RevA_HS_V (R60.1), PMP31236RevA_HS_W (R98.1), PMP31236RevA_LS_U (R134.1), PMP31236RevA_LS_V (R177.1), PMP31236RevA_LS_W (R220.1), PMP31236RevA_Interface (J1.b12)
GD0: PMP31236RevA_HS_U (R14.1), PMP31236RevA_HS_V (R52.1), PMP31236RevA_HS_W (R90.1), PMP31236RevA_LS_U (R128.1), PMP31236RevA_LS_V (R171.1), PMP31236RevA_LS_W (R214.1), PMP31236RevA_Interface (U13.8)
GD1: PMP31236RevA_HS_U (R15.1), PMP31236RevA_HS_V (R53.1), PMP31236RevA_HS_W (R91.1), PMP31236RevA_LS_U (R129.1), PMP31236RevA_LS_V (R172.1), PMP31236RevA_LS_W (R215.1), PMP31236RevA_Interface (U13.3 U13.4)
GD2: PMP31236RevA_HS_U (R18.1), PMP31236RevA_HS_V (R56.1), PMP31236RevA_HS_W (R94.1), PMP31236RevA_LS_U (R130.1), PMP31236RevA_LS_V (R173.1), PMP31236RevA_LS_W (R216.1), PMP31236RevA_Interface (U14.11)
HS_DO_PWM_U: PMP31236RevA_HS_U (R5.1 TP5.1), PMP31236RevA_Interface (J1.a5)
HS_DO_PWM_V: PMP31236RevA_HS_V (R43.1 TP16.1), PMP31236RevA_Interface (J1.a9)
HS_DO_PWM_W: PMP31236RevA_HS_W (R81.1 TP26.1), PMP31236RevA_Interface (J1.a13)
LS_DO_PWM_U: PMP31236RevA_LS_U (R119.1 TP36.1), PMP31236RevA_Interface (J1.a7)
LS_DO_PWM_V: PMP31236RevA_LS_V (R162.1 TP47.1), PMP31236RevA_Interface (J1.a11)
LS_DO_PWM_W: PMP31236RevA_LS_W (R205.1 TP58.1), PMP31236RevA_Interface (J1.a15)
nFLT1_HS_U: PMP31236RevA_HS_U (R2.1 R8.1), PMP31236RevA_Interface (J1.b6)
nFLT1_HS_V: PMP31236RevA_HS_V (R40.1 R46.1), PMP31236RevA_Interface (J1.b8)
nFLT1_HS_W: PMP31236RevA_HS_W (R78.1 R84.1), PMP31236RevA_Interface (J1.b10)
nFLT1_LS_U: PMP31236RevA_LS_U (R116.1 R122.1), PMP31236RevA_Interface (J1.b7)
nFLT1_LS_V: PMP31236RevA_LS_V (R159.1 R165.1), PMP31236RevA_Interface (J1.b9)
nFLT1_LS_W: PMP31236RevA_LS_W (R202.1 R208.1), PMP31236RevA_Interface (J1.b11)
SDO_HS_U: PMP31236RevA_HS_U (R34.1), PMP31236RevA_LS_V (R188.1)
SDO_HS_V: PMP31236RevA_HS_V (R72.1), PMP31236RevA_LS_W (R231.1)
SDO_LS_U: PMP31236RevA_HS_U (R31.1), PMP31236RevA_LS_U (R147.1)
SDO_LS_V: PMP31236RevA_HS_V (R69.1), PMP31236RevA_LS_V (R190.1)
SDO_LS_W: PMP31236RevA_HS_W (R107.1), PMP31236RevA_LS_W (R233.1)
SPI_CS: PMP31236RevA_HS_U (R35.1), PMP31236RevA_HS_V (R73.1), PMP31236RevA_HS_W (R111.1), PMP31236RevA_LS_U (R148.1), PMP31236RevA_LS_V (R191.1), PMP31236RevA_LS_W (R234.1), PMP31236RevA_Interface (J1.b16)
SPI_MISO: PMP31236RevA_HS_W (R110.1), PMP31236RevA_Interface (J1.b13 R294.1)
SPI_MOSI: PMP31236RevA_LS_U (R145.1), PMP31236RevA_Interface (J1.b15 R295.2)
SPI_SCLK: PMP31236RevA_HS_U (R28.1), PMP31236RevA_HS_V (R66.1), PMP31236RevA_HS_W (R104.1), PMP31236RevA_LS_U (R142.1), PMP31236RevA_LS_V (R185.1), PMP31236RevA_LS_W (R228.1), PMP31236RevA_Interface (J1.b14)
VSUP_GATE_BIAS: PMP31236RevA_Interface (J1.b2 J1.b3 J1.b4), PMP31236RevA_Supply_U (16 pins), PMP31236RevA_Supply_V (16 pins), PMP31236RevA_Supply_W (16 pins)
VSUP_PRIM: PMP31236RevA_HS_U (R1.1 R2.2 R3.2 R19.2), PMP31236RevA_HS_V (R39.1 R40.2 R41.2 R57.2), PMP31236RevA_HS_W (R77.1 R78.2 R79.2 R95.2), PMP31236RevA_LS_U (R115.1 R116.2 R117.2 R131.2), PMP31236RevA_LS_V (R158.1 R159.2 R160.2 R174.2), PMP31236RevA_LS_W (R201.1 R202.2 R203.2 R217.2), PMP31236RevA_Interface (8 pins)

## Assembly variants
Assembly PMP31236: not fitted Q1 Q2 Q3 Q4 Q5 Q6 Q7 R19 R24 R27 R57 R62 R65 R95 R100 R103 R131 R139 R141 R174 R182 R184 R217 R225 R227 R249 R257 R265 R273 R281 R289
